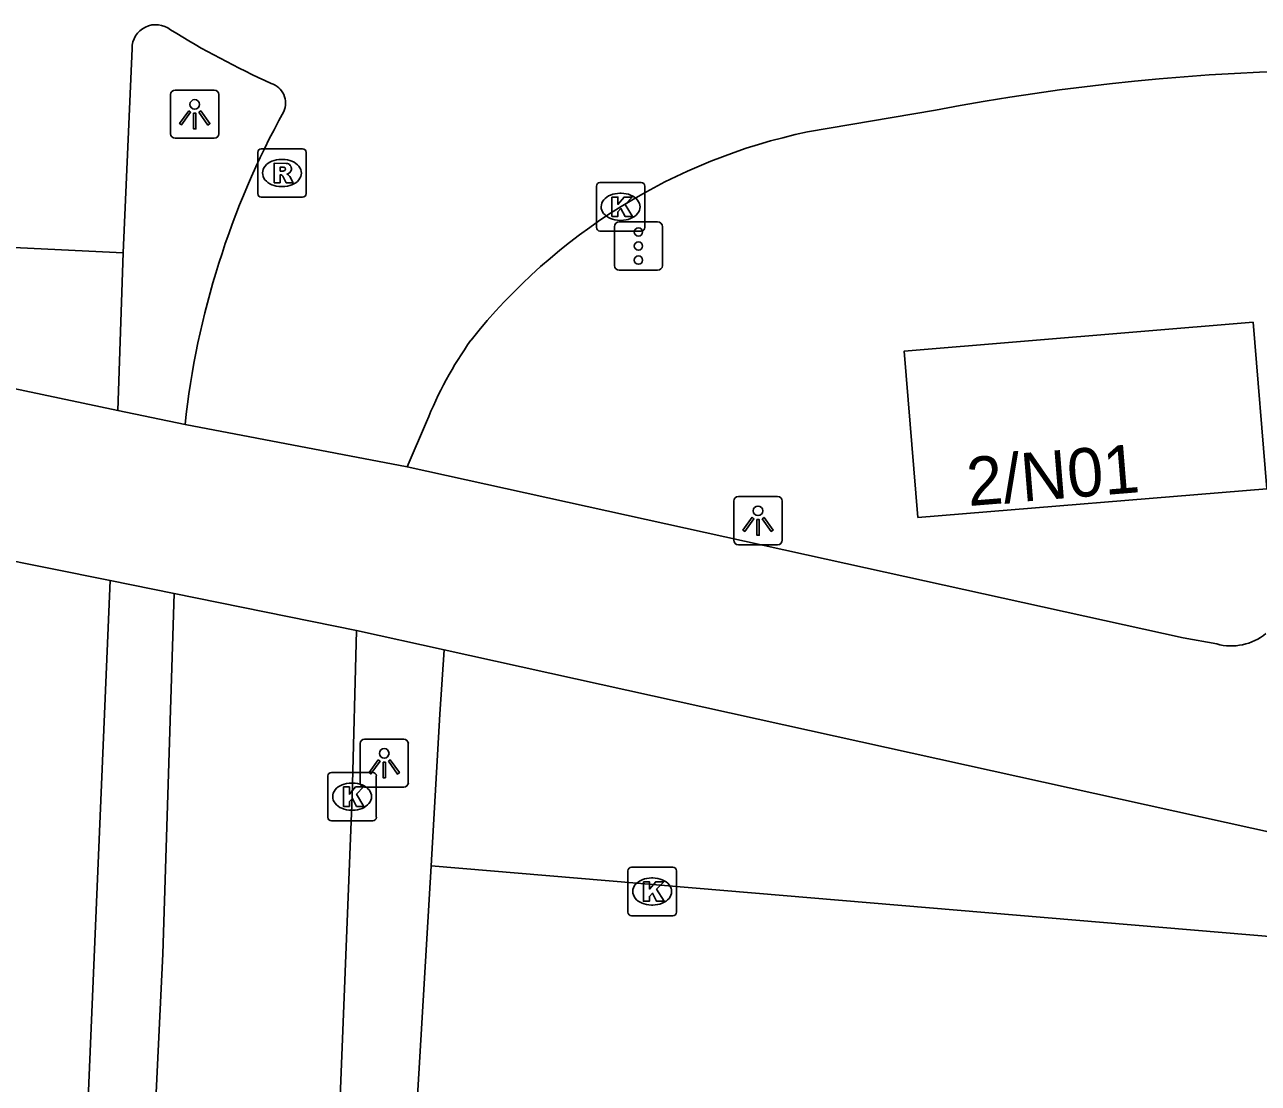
# Model space of a CAD drawing. Extents: x 161094 to 161705, y 379509 to 380907.
# Drawn here: x 161453.8 to 161479.27, y 379787.98 to 379809.82 of the extents above; entities that cross this region are included whole.
import ezdxf

# ---------------------------------------------------------------- set-up
doc = ezdxf.new("R2010")
doc.units = 0
for name, color, linetype in [('IMGEO_Fietspad_gesloten', 7, 'Continuous'), ('IMGEO_Groenvoorziening', 7, 'Continuous'), ('IMGEO_Kolk', 7, 'Continuous'), ('IMGEO_Lichtpunt', 7, 'Continuous'), ('IMGEO_Pand', 7, 'Continuous'), ('IMGEO_Pand_nummerreeks', 7, 'Continuous'), ('IMGEO_Rijbaan_lokaal_gesloten', 7, 'Continuous'), ('IMGEO_Rijbaan_lokaal_open', 7, 'Continuous'), ('IMGEO_Rioolput', 7, 'Continuous'), ('IMGEO_Verkeersregelinstallatiepaal', 7, 'Continuous')]:
    doc.layers.add(name, color=color, linetype=linetype)

msp = doc.modelspace()

# ---------------------------------------------------------------- linework, layer by layer
at = {"layer": 'IMGEO_Fietspad_gesloten'}
for points in [[(161457.114, 379801.568), (161455.727, 379801.86)], [(161478.409, 379797.042), (161477.716, 379797.168), (161461.697, 379800.699)], [(161455.565, 379798.35), (161456.891, 379798.083)], [(161462.462, 379796.924), (161460.655, 379797.323)], [(161462.462, 379796.924), (161483.43, 379792.296), (161487.83, 379791.325), (161496.812, 379789.457), (161497.951, 379789.22)]]:
    msp.add_lwpolyline(points, dxfattribs=at)
msp.add_arc((161478.707, 379798.14), 1.138, 254.7976, 309.0991, dxfattribs=at)
at = {"layer": 'IMGEO_Groenvoorziening'}
msp.add_lwpolyline([(161462.191, 379792.466), (161462.375, 379795.591), (161462.462, 379796.924)], dxfattribs=at)
at = {"layer": 'IMGEO_Kolk'}
for p, q in [((161465.603, 379805.635), (161465.603, 379806.487)), ((161465.678, 379806.561), (161466.53, 379806.561)), ((161466.604, 379806.487), (161466.604, 379805.635)), ((161466.091, 379806.341), (161466.116, 379806.341)), ((161466.114, 379805.781), (161466.089, 379805.781)), ((161466.53, 379805.561), (161465.678, 379805.561)), ((161460.136, 379794.393), (161460.988, 379794.393)), ((161460.061, 379793.467), (161460.061, 379794.319)), ((161460.549, 379794.173), (161460.574, 379794.173)), ((161461.062, 379794.319), (161461.062, 379793.467)), ((161460.988, 379793.393), (161460.136, 379793.393)), ((161460.572, 379793.613), (161460.547, 379793.613)), ((161466.255, 379791.51), (161466.255, 379792.362)), ((161466.33, 379792.436), (161467.182, 379792.436)), ((161467.256, 379792.362), (161467.256, 379791.51)), ((161466.743, 379792.216), (161466.768, 379792.216)), ((161466.766, 379791.656), (161466.741, 379791.656)), ((161467.182, 379791.436), (161466.33, 379791.436))]:
    msp.add_line(p, q, dxfattribs=at)
for points in [[(161465.603, 379805.635), (161465.603, 379806.487)], [(161465.678, 379806.561), (161466.53, 379806.561)], [(161466.604, 379806.487), (161466.604, 379805.635)], [(161465.924, 379806.261), (161466.047, 379806.261), (161466.047, 379806.11), (161466.177, 379806.261), (161466.341, 379806.261), (161466.195, 379806.11), (161466.348, 379805.861), (161466.196, 379805.861), (161466.111, 379806.025), (161466.047, 379805.958), (161466.047, 379805.861), (161465.924, 379805.861), (161465.924, 379806.261)], [(161466.53, 379805.561), (161465.678, 379805.561)], [(161460.136, 379794.393), (161460.988, 379794.393)], [(161460.061, 379793.467), (161460.061, 379794.319)], [(161461.062, 379794.319), (161461.062, 379793.467)], [(161460.382, 379794.093), (161460.505, 379794.093), (161460.505, 379793.942), (161460.635, 379794.093), (161460.799, 379794.093), (161460.653, 379793.942), (161460.806, 379793.693), (161460.654, 379793.693), (161460.569, 379793.857), (161460.505, 379793.79), (161460.505, 379793.693), (161460.382, 379793.693), (161460.382, 379794.093)], [(161460.988, 379793.393), (161460.136, 379793.393)], [(161466.255, 379791.51), (161466.255, 379792.362)], [(161466.33, 379792.436), (161467.182, 379792.436)], [(161467.256, 379792.362), (161467.256, 379791.51)], [(161466.576, 379792.136), (161466.699, 379792.136), (161466.699, 379791.985), (161466.829, 379792.136), (161466.993, 379792.136), (161466.847, 379791.985), (161467, 379791.736), (161466.848, 379791.736), (161466.763, 379791.9), (161466.699, 379791.833), (161466.699, 379791.736), (161466.576, 379791.736), (161466.576, 379792.136)], [(161467.182, 379791.436), (161466.33, 379791.436)]]:
    msp.add_lwpolyline(points, dxfattribs=at)
for centre, start, end in [((161465.68, 379806.485), 91.552, 178.448), ((161465.68, 379806.485), 91.552, 178.448), ((161466.528, 379806.485), 1.552, 88.448), ((161466.528, 379806.485), 1.552, 88.448), ((161465.68, 379805.637), 181.552, 268.448), ((161465.68, 379805.637), 181.552, 268.448), ((161466.528, 379805.637), 271.552, 358.448), ((161466.528, 379805.637), 271.552, 358.448), ((161460.138, 379794.317), 91.552, 178.448), ((161460.138, 379794.317), 91.552, 178.448), ((161460.986, 379794.317), 1.552, 88.448), ((161460.986, 379794.317), 1.552, 88.448), ((161460.138, 379793.469), 181.552, 268.448), ((161460.138, 379793.469), 181.552, 268.448), ((161460.986, 379793.469), 271.552, 358.448), ((161460.986, 379793.469), 271.552, 358.448), ((161466.332, 379792.36), 91.552, 178.448), ((161466.332, 379792.36), 91.552, 178.448), ((161467.18, 379792.36), 1.552, 88.448), ((161467.18, 379792.36), 1.552, 88.448), ((161466.332, 379791.512), 181.552, 268.448), ((161466.332, 379791.512), 181.552, 268.448), ((161467.18, 379791.512), 271.552, 358.448), ((161467.18, 379791.512), 271.552, 358.448)]:
    msp.add_arc(centre, 0.0765, start, end, dxfattribs=at)
for centre, major_axis, ratio, start_param, end_param in [((161466.09, 379806.061), (-0.387, 0.002), 0.722429, 4.712389, 7.853982), ((161466.115, 379806.061), (-0.39, 0.002), 0.717154, 1.570796, 4.712389), ((161460.548, 379793.893), (-0.387, 0.002), 0.722429, 4.712389, 7.853982), ((161460.573, 379793.893), (-0.39, 0.002), 0.717154, 1.570796, 4.712389), ((161466.742, 379791.936), (-0.387, 0.002), 0.722429, 4.712389, 7.853982), ((161466.767, 379791.936), (-0.39, 0.002), 0.717154, 1.570796, 4.712389)]:
    msp.add_ellipse(centre, major_axis=major_axis, ratio=ratio, start_param=start_param, end_param=end_param, dxfattribs=at)
at = {"layer": 'IMGEO_Lichtpunt'}
for p, q in [((161457.717, 379808.47), (161456.909, 379808.47)), ((161457.717, 379808.47), (161456.909, 379808.47)), ((161456.815, 379808.375), (161456.815, 379807.568)), ((161456.815, 379808.375), (161456.815, 379807.568)), ((161457.811, 379807.568), (161457.811, 379808.375)), ((161457.811, 379807.568), (161457.811, 379808.375)), ((161456.909, 379807.474), (161457.717, 379807.474)), ((161456.909, 379807.474), (161457.717, 379807.474)), ((161468.442, 379799.991), (161468.442, 379799.184)), ((161468.442, 379799.991), (161468.442, 379799.184)), ((161469.344, 379800.086), (161468.536, 379800.086)), ((161469.344, 379800.086), (161468.536, 379800.086)), ((161469.438, 379799.184), (161469.438, 379799.991)), ((161469.438, 379799.184), (161469.438, 379799.991)), ((161468.536, 379799.09), (161469.344, 379799.09)), ((161468.536, 379799.09), (161469.344, 379799.09)), ((161460.726, 379794.987), (161460.726, 379794.18)), ((161460.726, 379794.987), (161460.726, 379794.18)), ((161461.628, 379795.082), (161460.82, 379795.082)), ((161461.628, 379795.082), (161460.82, 379795.082)), ((161461.722, 379794.18), (161461.722, 379794.987)), ((161461.722, 379794.18), (161461.722, 379794.987)), ((161460.82, 379794.086), (161461.628, 379794.086)), ((161460.82, 379794.086), (161461.628, 379794.086))]:
    msp.add_line(p, q, dxfattribs=at)
for points in [[(161457.189, 379808.039), (161457.228, 379808.011), (161457.04, 379807.749), (161457.002, 379807.776), (161457.189, 379808.039)], [(161457.291, 379807.991), (161457.338, 379807.991), (161457.338, 379807.669), (161457.291, 379807.669), (161457.291, 379807.991)], [(161457.401, 379808.011), (161457.439, 379808.038), (161457.626, 379807.776), (161457.587, 379807.748), (161457.401, 379808.011)], [(161468.816, 379799.655), (161468.855, 379799.627), (161468.667, 379799.365), (161468.629, 379799.392), (161468.816, 379799.655)], [(161468.918, 379799.607), (161468.965, 379799.607), (161468.965, 379799.285), (161468.918, 379799.285), (161468.918, 379799.607)], [(161469.028, 379799.627), (161469.066, 379799.654), (161469.253, 379799.392), (161469.214, 379799.364), (161469.028, 379799.627)], [(161461.1, 379794.651), (161461.139, 379794.623), (161460.951, 379794.361), (161460.913, 379794.388), (161461.1, 379794.651)], [(161461.312, 379794.623), (161461.35, 379794.65), (161461.537, 379794.388), (161461.498, 379794.36), (161461.312, 379794.623)], [(161461.202, 379794.603), (161461.249, 379794.603), (161461.249, 379794.281), (161461.202, 379794.281), (161461.202, 379794.603)]]:
    msp.add_lwpolyline(points, dxfattribs=at)
for centre in [(161457.314, 379808.173), (161468.941, 379799.789), (161461.225, 379794.785)]:
    msp.add_circle(centre, 0.0994, dxfattribs=at)
for centre, start, end in [((161456.909, 379808.375), 90, 180), ((161456.909, 379808.375), 90, 180), ((161457.717, 379808.375), 0, 90), ((161457.717, 379808.375), 0, 90), ((161456.909, 379807.568), 180, 270), ((161456.909, 379807.568), 180, 270), ((161457.717, 379807.568), 270, 0), ((161457.717, 379807.568), 270, 360), ((161468.536, 379799.991), 90, 180), ((161468.536, 379799.991), 90, 180), ((161469.344, 379799.991), 0, 90), ((161469.344, 379799.991), 0, 90), ((161468.536, 379799.184), 180, 270), ((161468.536, 379799.184), 180, 270), ((161469.344, 379799.184), 270, 0), ((161469.344, 379799.184), 270, 360), ((161460.82, 379794.987), 90, 180), ((161460.82, 379794.987), 90, 180), ((161461.628, 379794.987), 0, 90), ((161461.628, 379794.987), 0, 90), ((161460.82, 379794.18), 180, 270), ((161460.82, 379794.18), 180, 270), ((161461.628, 379794.18), 270, 0), ((161461.628, 379794.18), 270, 360)]:
    msp.add_arc(centre, 0.0946, start, end, dxfattribs=at)
at = {"layer": 'IMGEO_Pand'}
msp.add_lwpolyline([(161472.241, 379799.654), (161479.44, 379800.246), (161479.158, 379803.678), (161471.959, 379803.086), (161472.241, 379799.654)], dxfattribs=at)
at = {"layer": 'IMGEO_Rijbaan_lokaal_gesloten'}
for points in [[(161455.836, 379805.108), (161456.019, 379809.326)], [(161469.963, 379807.607), (161472.604, 379808.056)], [(161452.02, 379805.298), (161455.836, 379805.108)], [(161455.727, 379801.86), (161455.836, 379805.108)], [(161455.727, 379801.86), (161451.884, 379802.669)], [(161457.114, 379801.568), (161461.697, 379800.699)], [(161461.697, 379800.699), (161462.098, 379801.624)], [(161460.973, 379767.378), (161461.725, 379784.582), (161462.191, 379792.466)], [(161483.335, 379790.687), (161462.191, 379792.466)]]:
    msp.add_lwpolyline(points, dxfattribs=at)
for centre, radius, start, end in [((161456.509, 379809.328), 0.49, 51.2716, 180.2349), ((161466.524, 379825.439), 18.484, 238.3153, 245.6142), ((161481.255, 379762.958), 45.92, 80.177, 100.8587), ((161458.768, 379808.201), 0.422, 335.4898, 72.9492), ((161474.202, 379799.726), 17.187, 151.1231, 173.8478), ((161472.434, 379795.849), 12.014, 101.8694, 141.6195), ((161469.541, 379798.661), 8.011, 144.5398, 158.2964)]:
    msp.add_arc(centre, radius, start, end, dxfattribs=at)
at = {"layer": 'IMGEO_Rijbaan_lokaal_open'}
for points in [[(161451.795, 379799.111), (161455.565, 379798.35)], [(161455.074, 379786.688), (161455.243, 379790.742), (161455.565, 379798.35)], [(161456.891, 379798.083), (161456.655, 379790.65), (161456.461, 379786.641)], [(161456.891, 379798.083), (161460.655, 379797.323)], [(161460.655, 379797.323), (161460.562, 379793.893), (161460.175, 379784.242)]]:
    msp.add_lwpolyline(points, dxfattribs=at)
at = {"layer": 'IMGEO_Rioolput'}
for p, q in [((161458.613, 379806.332), (161458.613, 379807.184)), ((161458.688, 379807.258), (161459.54, 379807.258)), ((161459.614, 379807.184), (161459.614, 379806.332)), ((161459.101, 379807.038), (161459.126, 379807.038)), ((161459.124, 379806.478), (161459.099, 379806.478)), ((161459.54, 379806.258), (161458.688, 379806.258))]:
    msp.add_line(p, q, dxfattribs=at)
for points in [[(161458.613, 379806.332), (161458.613, 379807.184)], [(161458.688, 379807.258), (161459.54, 379807.258)], [(161459.614, 379807.184), (161459.614, 379806.332)], [(161459.202, 379806.956), (161458.95, 379806.958), (161458.95, 379806.558)], [(161459.128, 379806.877), (161459.074, 379806.877), (161459.074, 379806.796)], [(161458.95, 379806.558), (161459.074, 379806.558), (161459.074, 379806.72), (161459.085, 379806.72)], [(161459.074, 379806.796), (161459.126, 379806.796)], [(161459.132, 379806.691), (161459.203, 379806.558), (161459.343, 379806.558), (161459.278, 379806.684)], [(161459.54, 379806.258), (161458.688, 379806.258)]]:
    msp.add_lwpolyline(points, dxfattribs=at)
for centre, radius, start, end in [((161458.69, 379807.182), 0.0765, 91.552, 178.448), ((161458.69, 379807.182), 0.0765, 91.552, 178.448), ((161459.538, 379807.182), 0.0765, 1.552, 88.448), ((161459.538, 379807.182), 0.0765, 1.552, 88.448), ((161459.134, 379806.781), 0.0964, 77.0061, 93.1865), ((161459.148, 379806.838), 0.0378, 276.6634, 79.6772), ((161459.201, 379806.846), 0.109, 350.3612, 89.416), ((161459.084, 379806.667), 0.0533, 26.0293, 88.6989), ((161459.11, 379806.985), 0.19, 274.7715, 282.9687), ((161459.199, 379806.846), 0.112, 277.5842, 350.9817), ((161459.183, 379806.631), 0.108, 29.5134, 73.7905), ((161458.69, 379806.334), 0.0765, 181.552, 268.448), ((161458.69, 379806.334), 0.0765, 181.552, 268.448), ((161459.538, 379806.334), 0.0765, 271.552, 358.448), ((161459.538, 379806.334), 0.0765, 271.552, 358.448)]:
    msp.add_arc(centre, radius, start, end, dxfattribs=at)
for centre, major_axis, ratio, start_param, end_param in [((161459.1, 379806.758), (-0.387, 0.002), 0.722429, 4.712389, 7.853982), ((161459.125, 379806.758), (-0.39, 0.002), 0.717154, 1.570796, 4.712389)]:
    msp.add_ellipse(centre, major_axis=major_axis, ratio=ratio, start_param=start_param, end_param=end_param, dxfattribs=at)
at = {"layer": 'IMGEO_Verkeersregelinstallatiepaal'}
for p, q in [((161465.977, 379804.851), (161465.977, 379805.651)), ((161465.977, 379805.651), (161465.977, 379804.851)), ((161466.077, 379805.751), (161466.867, 379805.751)), ((161466.867, 379805.751), (161466.077, 379805.751)), ((161466.967, 379805.651), (161466.967, 379804.851)), ((161466.967, 379804.851), (161466.967, 379805.651)), ((161466.867, 379804.751), (161466.077, 379804.751)), ((161466.077, 379804.751), (161466.867, 379804.751))]:
    msp.add_line(p, q, dxfattribs=at)
for centre in [(161466.472, 379805.541), (161466.472, 379805.251), (161466.472, 379804.961)]:
    msp.add_circle(centre, 0.085, dxfattribs=at)
for centre, start, end in [((161466.077, 379805.651), 90, 180), ((161466.077, 379805.651), 90, 180), ((161466.867, 379805.651), 0, 90), ((161466.867, 379805.651), 360, 90), ((161466.077, 379804.851), 180, 270), ((161466.077, 379804.851), 180, 270), ((161466.867, 379804.851), 270, 0), ((161466.867, 379804.851), 270, 0)]:
    msp.add_arc(centre, 0.1, start, end, dxfattribs=at)

# ---------------------------------------------------------------- texts
at = {"layer": 'IMGEO_Pand_nummerreeks'}
msp.add_text('2/N01', height=1, rotation=4.6583, dxfattribs=at).set_placement((161473.287, 379799.886))

doc.saveas('drawing.dxf')
